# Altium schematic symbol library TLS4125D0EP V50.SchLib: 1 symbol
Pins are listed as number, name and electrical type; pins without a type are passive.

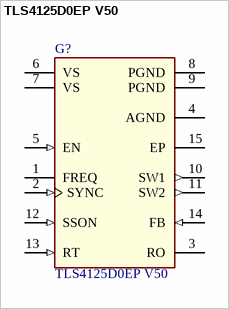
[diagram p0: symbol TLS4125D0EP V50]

## TLS4125D0EP V50
designator G?
Synchronous Step-Down Regulator; Manufacturer: Infineon Technologies; PacakageReference: PG-TSDSO-14-5
pins: 1 FREQ "Frequency Selection", 2 SYNC (in) "Synchronization Input", 3 RO (oc) "Reset Output", 4 AGND (power) "Analog Ground", 5 EN (in) "Enable Input", 6 VS (power) "Supply Voltage Input", 7 VS (power) "Supply Voltage Input", 8 PGND (power) "Power Ground", 9 PGND (power) "Power Ground", 10 SW1 (out) "Buck Switch Output", 11 SW2 (out) "Buck Switch Output", 12 SSON (in) "Spread Spectrum ON/OFF", 13 RT (in) "Reset Configuration", 14 FB (in) "Feedback Input", 15 EP (power) "Exposed Pad"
